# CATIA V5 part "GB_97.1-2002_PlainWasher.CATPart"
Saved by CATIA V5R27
Part number: GB/T 97.1-2002 平垫圈
Bounding box of the stored display mesh (mm): x -10 to 10, y -10 to 10, z 0 to 2
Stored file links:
  E:\资料\Catia超级副本\GB 97.1-2002 平垫圈\GB_97.1-2002_PlainWasher.CATPart
  E:\资料\Catia超级副本\GB 97.1-2002 平垫圈\GB97.1-2002_PlainWasher_DesignTable.xlsx
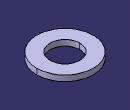
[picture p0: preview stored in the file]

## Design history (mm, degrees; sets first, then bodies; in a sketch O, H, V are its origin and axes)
Parameters
  d1 = 10.5 mm {design table}
  d2 = 20 mm {design table}
  h = 2 mm {design table}
  `公称直径d` = 10 mm {design table}
AxisSystem1: origin (0, 0, 0), X (1, 0, 0), Y (0, 1, 0), Z (0, 0, 1)
Set1 "输入参数"
  Point1: (0, 0, 0), in AxisSystem1
  Plane1: type Normal, Curve Line1, RefPoint Point1, Ratio 0
Body1 (main body)
  Sketch1 on Plane1, origin (0, 0, 0), H (1, 0, 0), V (0, 1, 0)
    circle A1 centre (0, 0) radius 5.25
    circle A2 centre (0, 0) radius 10
    radius A1 = 5.25 {= d1 /2}
    radius A2 = 10 {= d2 /2}
    concentricity: A2 A1
  Pad1: profile Sketch1, direction (0, 0, 1), length 2 {= h}
  Set2
    Line1: type PtDir, RefPoint Point1, Direction (0, 0, 1), Start 0, End 20
Relations
  design table, configuration 9, drives d1, d2, h, `公称直径d`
